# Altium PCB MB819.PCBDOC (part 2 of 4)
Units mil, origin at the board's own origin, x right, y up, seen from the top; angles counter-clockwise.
Board outline 4505 x 6805 mil, 4 copper layers (TopLayer, MidLayer1, GND, BottomLayer), stack 69.6 mil thick; 336 components, 282 nets, 1318 pads, 584 vias.
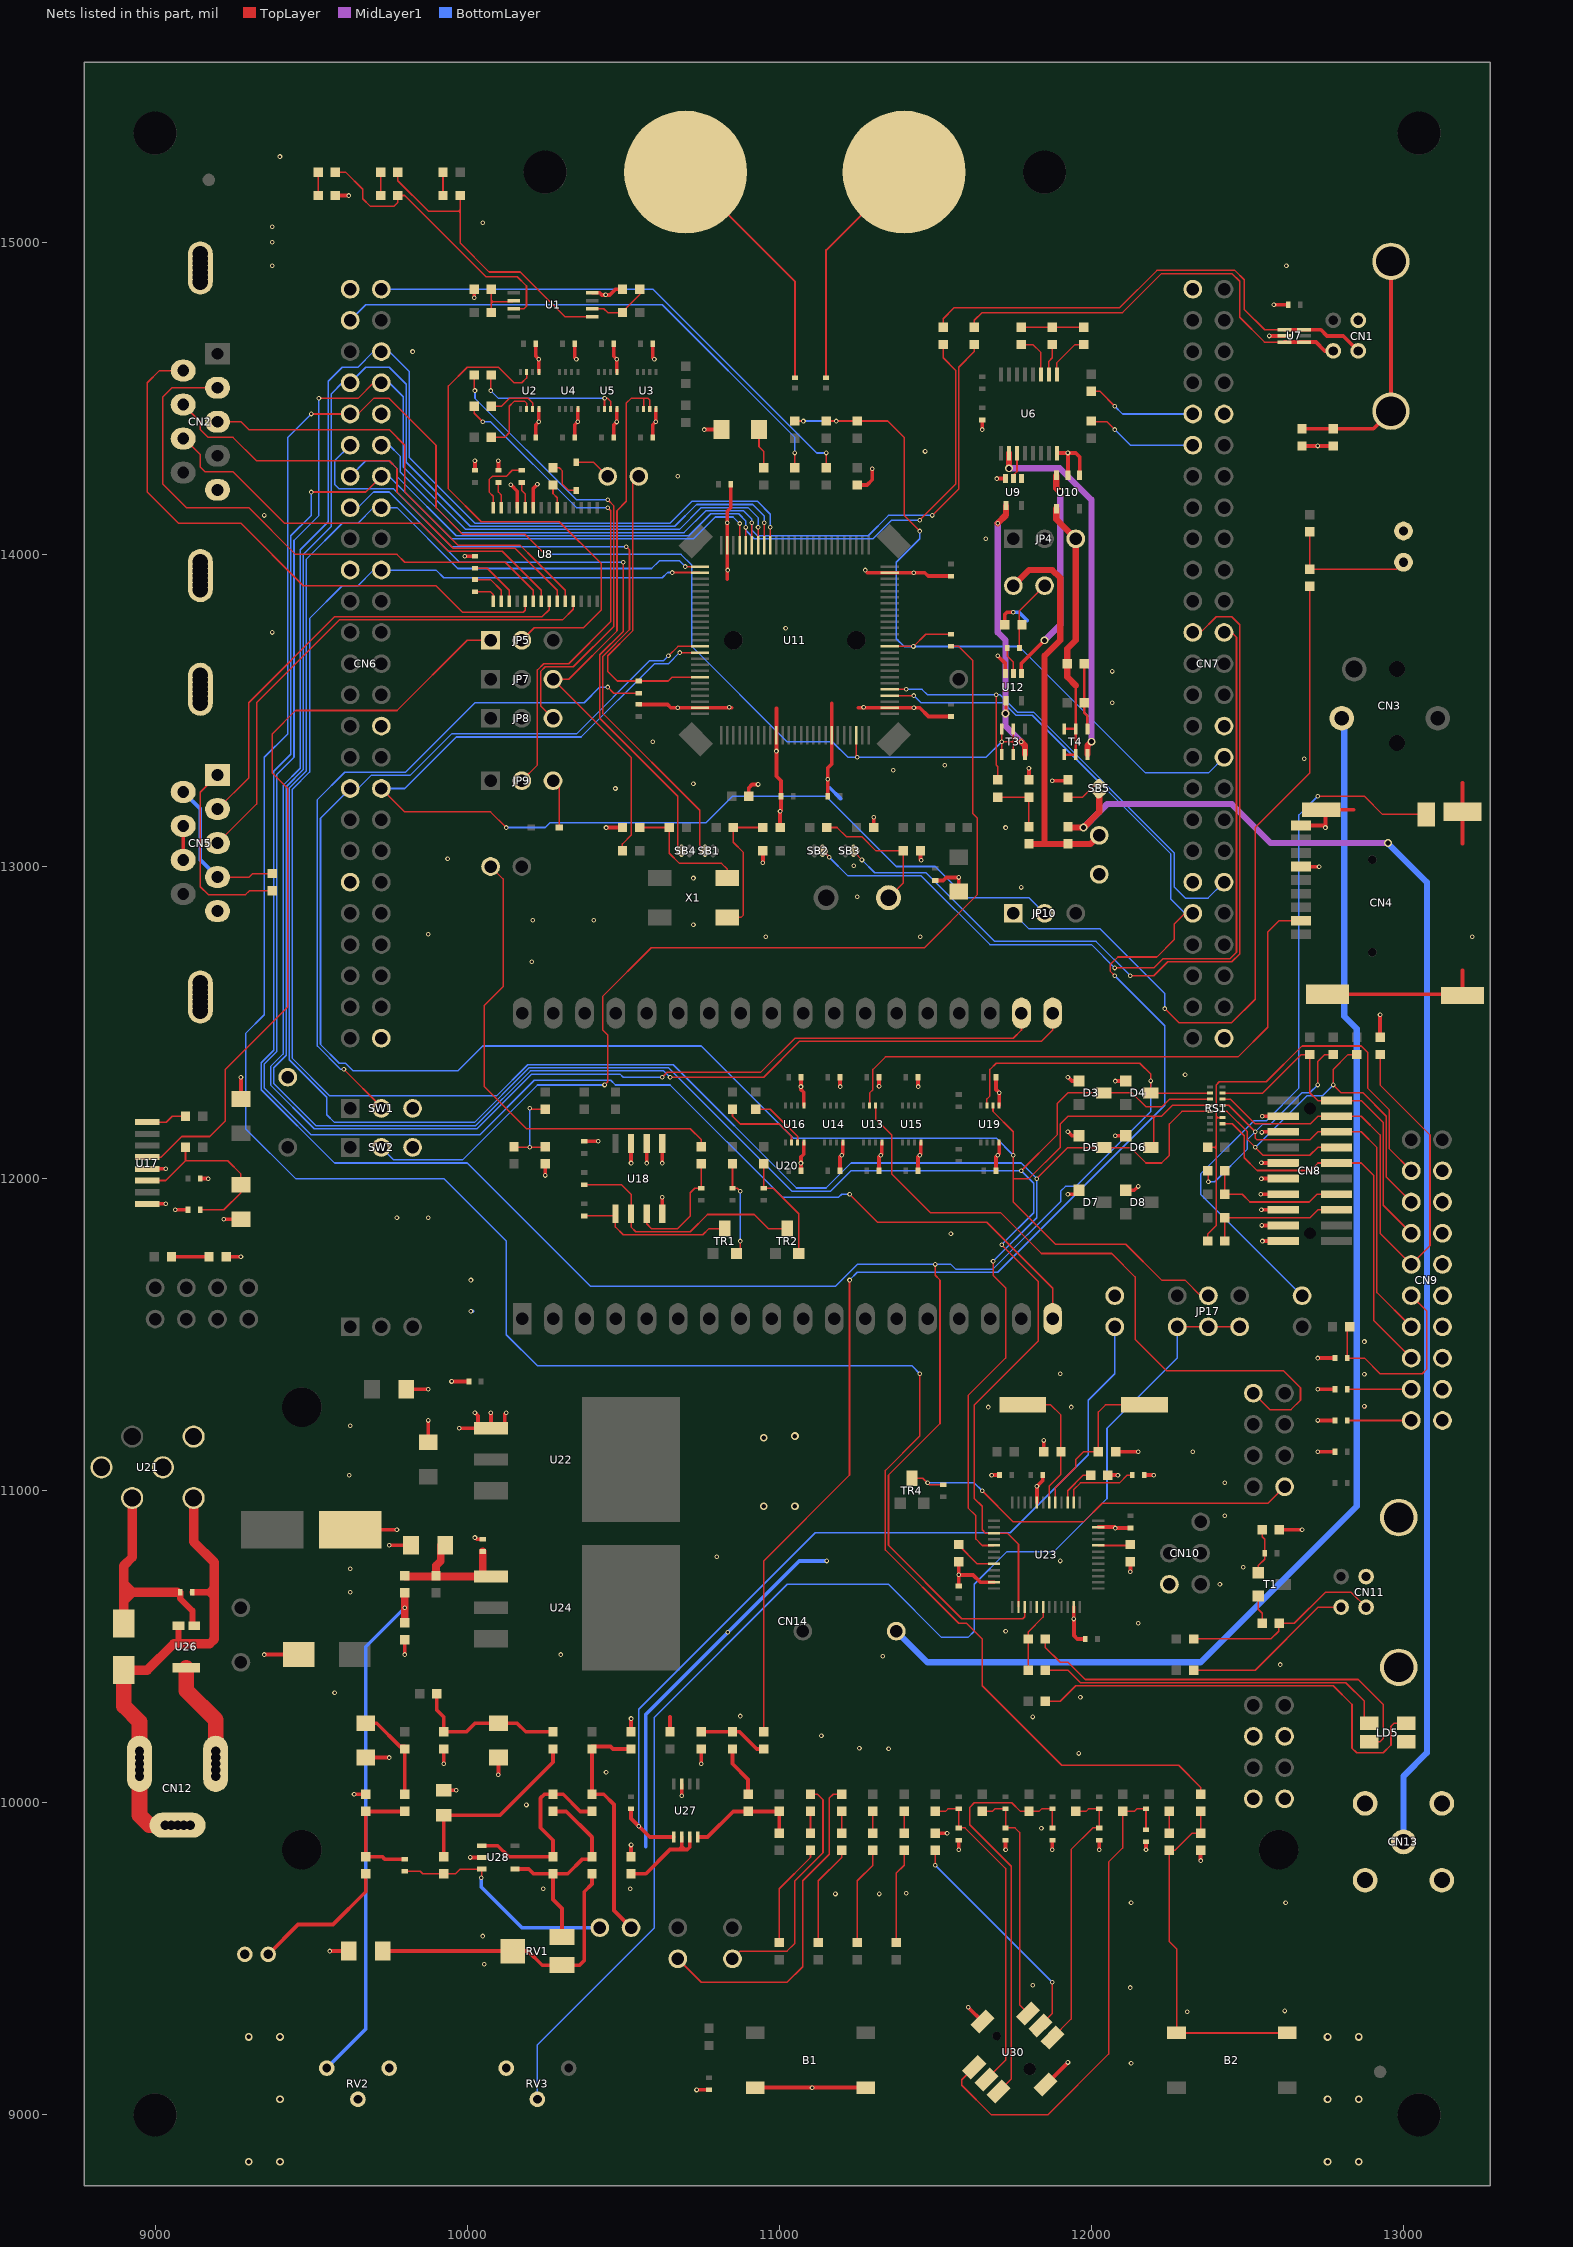
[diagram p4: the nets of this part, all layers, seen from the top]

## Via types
v1: diameter 15, hole 8, TopLayer to BottomLayer, tented both sides, 315 vias
v2: diameter 15, hole 8, TopLayer to BottomLayer, 230 vias
v3: diameter 25, hole 15, TopLayer to BottomLayer, tented both sides, 31 vias
v4: diameter 25, hole 16, TopLayer to BottomLayer, 6 vias
v5: diameter 25, hole 16, TopLayer to BottomLayer, tented both sides, 2 vias

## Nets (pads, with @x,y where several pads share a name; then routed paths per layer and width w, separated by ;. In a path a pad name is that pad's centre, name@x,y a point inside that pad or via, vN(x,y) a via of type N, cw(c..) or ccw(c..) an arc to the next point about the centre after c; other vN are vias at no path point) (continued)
GND: B1.1 B1.4 C1.1 C2.1 C3.1 C4.1 C5.2 C7.2 C8.2 C9.1 C10.1 C11.1 C12.1 C13.1 C14.1 C15.2 C17.2 C18.2 C20.2 C21.2 C22.2 C23.2 C24.2 C25.2 C26.2 C27.2 C28.2 C29.2 C30.2 C31.1 C32.2 C33.2 C34.2 C35.1 C36.1 C37.1 C38.1 C39.2 C40.2 C41.1 C42.1 C43.1 C44.2 C45.2 C46.1 C47.2 C48.2 C49.2 C50.1 C51.2 C52.2 C53.1 C54.1 C55.2 C56.1 C57.2 C58.2 C59.1 C62.1 C63.2 C64.1 C65.2 C66.2 C67.2 C68.2 C69.2 C70.1 C72.2 C73.2 C76.1 C77.1 C78.1 C79.1 C80.1 C83.2 C84.2 C85.1 CN1.4 CN2.0 CN2.5 CN4.6 CN4.9 CN4.G1 CN4.G2 CN4.G3 CN4.G4 CN5.0 CN5.5 CN6.1 CN6.10 CN6.19 CN6.30 CN6.39 CN6.50 CN7.1 CN7.10 CN7.30 CN7.39 CN7.50 CN8.3 CN8.5 CN8.9 CN8.11 CN8.13 CN8.15 CN8.17 CN8.19 CN9.4 CN9.6 CN9.8 CN9.10 CN9.12 CN9.14 CN9.16 CN9.18 CN9.20 CN10.2 CN11.0 CN11.4 CN13.1 CN13.2 CN13.3 CN13.4 CN14.11 CN14.12 CN14.15 CN14.16 D3.2 D4.2 D5.2 D6.2 D7.2 D8.2 JP16.2 LD5.1 LD9.2 R2.2 R4.1 R6.1 R8.2 R15.2 R27.1 R34.1 R40.1 R42.2 R54.1 R56.2 R79.1 R80.1 R81.2 R83.1 R84.1 R85.2 R89.1 R93.1 R100.2 R132.1 R134.2 RV2.1 RV2.2 RV3.3 SW1.3 SW2.3 TP2.1 TP4.1 U1.4 U2.4 U2.5 U3.4 U4.4 U5.4 U5.5 U6.8 U7.2 U8.23 U8.25 U9.3 U10.1 U10.2 U11.10 U11.19 U11.27 U11.49 U11.74 U11.99 U12.3 U13.4 U14.4 U15.4 U16.4 U16.5 U17.5 U17.8 U18.4 U18.5 U18.6 U18.7 U19.4 U19.5 U21.4 U21.5 U21.6 U22.1 U23.8 U23.23 U23.35 U23.47 U27.7 U28.2 U29.1 U30.G | length 11978.2
  TopLayer w12: U17.8@8975,11919.09 v1(9034.09,11919.09) ; U17.5@8975,12031.3 v1(9033.7,12031.3) ; v1(9065,11900) C47.2@9105.5,11900 ; C44.2@9144.5,12000 v1(9170,12000) ; v1(9220,11870) C48.2@9275,11870 ; LD9.2@9227.5,11750 v1(9275,11750) ; C40.2@9275,12255 v2(9275,12325) ; v1(9350,10475) C65.2@9460,10475 ; v1(9560,9525) C84.2@9620,9525 ; R2.2@9577.5,15150 v2(9620,15150) ; C58.2@9625,10875 v1(9775,10875) ; v1(9637.5,10027.5) C72.2@9675,10027.5 ; C67.2@9675,10145 v1(9750,10145) ; v2(9750,10825) C39.2@9820,10825 ; v1(9800,10475) R56.2@9800,10522.5 ; C52.2@9805,11325 v2(9875,11325) ; C55.2@9875,11155 v1(9875,11225) ; C73.2@9925,10040 v1(9965,10040) ; v1(9925,10125) R100.2@9925,10172.5 ; v1(9950,11350) C51.2@10005.5,11350 ; v2(9975,11200) U22.1@10076.18,11200 10076.18,11248.82 v2(10075,11250) ; v2(9992.5,13994.5) C20.2@10025,13994.5 ; v1(10010,9825) U28.2@10046.85,9825 ; v1(10022.5,14822.5) R4.1@10022.5,14850 ; v2(10025,10850) 10030.5,10844.5 C63.2@10050,10844.5 ; v2(10025,11250) 10035,11240 U22.1@10035,11200 ; C14.1@10025,14269.5 v1(10025,14300) ; v1(10100,10090) C68.2@10100,10145 ; C15.2@10100,14269.5 v2(10100,14300) ; U22.1@10120,11200 10120,11245 v2(10125,11250) ; v1(10140,14223) 10160.43,14202.57 U8.25@10160.43,14149.61 ; U8.23@10211.61,14149.61 10211.61,14211.61 v2(10225,14225) ; C8.2@10219.5,14375 10219.5,14414.97 v2(10229.53,14425) U2.4@10229.53,14465.94 ; C4.1@10219.5,14675 10219.5,14635.5 v1(10229.53,14625.47) U2.5@10229.53,14584.06 ; v2(10250,12010) R81.2@10250,12047.5 ; C9.1@10344.5,14375 10344.5,14415.44 v1(10354.53,14425.47) ; C1.1@10344.5,14675 10344.5,14630.5 v1(10350,14625) ; U4.4@10354.53,14465.94 v1(10354.53,14425.47) ; v1@10355,14425 v1(10354.53,14425.47) ; C41.1@10375.5,12120 v1(10420,12120) ; U1.4@10400.98,14838.39 10425,14838.39 10431.77,14831.61 10456.61,14831.61 10475,14850 R6.1@10497.5,14850 ; v1(10445,13125) C28.2@10497.5,13125 ; C10.1@10469.5,14375 10469.5,14414.5 v2(10479.53,14424.53) U5.4@10479.53,14465.94 ; C2.1@10469.5,14675 10469.5,14635.03 v1(10479.53,14625) U5.5@10479.53,14584.06 ; C83.2@10525,9827.5 v1(10525,9865) ; C69.2@10525,10227.5 v1(10525,10270) ; v1(10525,12050) U18.7@10525,12112.5 ; C23.2@10550,13519.5 10641.5,13519.5 10652.54,13508.46 v1@10846.54,13508.46 ; v1(10575,12050) U18.6@10575,12112.5 ; C12.1@10594.5,14375 10594.5,14415.44 v1(10604.53,14425.47) U3.4@10604.53,14465.94 ; C3.1@10594.5,14675 10594.5,14630.5 v1(10600,14625) ; U18.4@10625,11887.5 v1(10625,11940) ; v1@10625,12052.5 U18.5@10625,12115 ; C66.2@10650,10227.5 10650,10275 ; v1(10687.2,10022.2) U27.7@10687.2,10059.69 ; v1(10735,9080) 10735.5,9080.5 C85.1@10775,9080.5 ; v1(10750,10125) C70.1@10750,10172.5 ; v2(10760,14400) C11.1@10815,14400 ; 10833.46,13921.54 10833.46,14138.46 10844.5,14149.5 C17.2@10844.5,14225 ; C22.2@10902.5,13225 10902.5,13252.5 10913,13263 v1(10932.07,13263) ; B1.1@10922.83,9087.5 B1.4@11277.17,9087.5 ; v1(10947.5,13012.5) C30.2@10947.5,13050 ; 10990.94,13505.94 10990.94,13370.06 v1(10991,13370) 10991,13289 11005.5,13274.5 v1@11005.5,13180.5 ; C29.2@11002.5,13125 v1(11002.5,13177.5) ; C45.2@11069.5,12025 11069.5,12069.5 11075,12075 ; v1(11069.5,12295) v1@11070,12295 ; C38.1@11069.5,12325 11069.5,12285.5 11078.53,12276.47 U16.5@11078.53,12234.06 ; 11078.53,12078.53 U16.4@11078.53,12115.94 ; C27.2@11155.5,13225 11155.5,13315.5 11168.11,13328.11 11168.11,13523.11 ; C46.1@11194.5,12025 11194.5,12069.5 v2(11200,12075) ; C35.1@11194.5,12325 11194.5,12295.5 v1(11195,12295) ; v2@11203.53,12078.53 U14.4@11203.53,12115.94 ; C18.2@11250,14222.5 11281.5,14222.5 11298,14239 v1(11298,14275) ; 11253.46,13508.46 11450,13508.46 11477.96,13480.5 C24.2@11550,13480.5 ; 11281.54,13941.54 11466,13941.54 11477.04,13930.5 C21.2@11550,13930.5 ; R40.1@11302.5,13125 v1(11302.5,13157.5) ; C42.1@11319.5,12025 11319.5,12069.5 v2(11325,12075) ; v1(11319.5,12295.5) C36.1@11319.5,12325 ; v2@11328.53,12078.53 U13.4@11328.53,12115.94 ; C43.1@11444.5,12025 11444.5,12069.5 11453.53,12078.53 U15.4@11453.53,12115.94 ; C37.1@11444.5,12325 11444.5,12295.5 v1(11445,12295) ; C33.2@11452.5,13050 11452.5,13022.5 v1(11455,13020) ; R132.1@11500,9902.5 v1(11537.5,9902.5) ; C32.2@11500,12955.5 11525.5,12955.5 11535,12965 v1(11575,12965) C34.2@11575,12920 ; v1(11575,9850) C76.1@11575,9880.5 ; C62.1@11575,10694.5 R15.2@11575,10772.5 ; v2@11575,10730 11621,10730 11644.58,10706.42 U23.23@11687.68,10706.42 ; v2(11605,9345) U30.G@11651,9298.99 ; v2(11650,14400) C7.2@11650,14430.5 ; v1(11680,11050) C56.1@11705.5,11050 ; C50.1@11694.5,12025 11694.5,12069.5 v2(11700,12075) ; C49.2@11694.5,12325 11694.5,12285.5 v2(11704.53,12275.47) U19.5@11704.53,12234.06 ; v1(11697,14243) 11697.31,14243.31 U9.3@11724.41,14243.31 ; v1(11700,13675) 11724.41,13650.59 U12.3@11724.41,13618.31 ; v2@11704.53,12079.53 U19.4@11704.53,12115.94 ; C25.2@11722.5,13775 11722.5,13807.5 11730,13815 v2(11750,13815) ; v1(11725,9850) C77.1@11725,9880.5 ; C31.1@11800,13277.5 v2(11800,13315) ; U23.8@11825.47,10962.32 v1(11825.47,11014.47) 11844.5,11033.5 C57.2@11844.5,11050 ; v1@11826,11015 v1@11827,11015 ; v1(11847,11161) 11847.5,11160.5 C53.1@11847.5,11125 ; U30.G@11852.53,9097.47 11854.47,9097.47 v1(11925,9168) ; v1(11875,9850) C78.1@11875,9880.5 ; v1(11875,13275) R42.2@11922.5,13275 ; U6.8@11890.55,14325 11950,14325 11962.4,14312.6 U10.1@11962.4,14253.15 ; v1(11925,11950) D7.2@11960,11950 ; v2(11925,12150) 11937.5,12137.5 D5.2@11960,12137.5 ; v2(11925,12325) 11937.5,12312.5 D3.2@11960,12312.5 ; U10.2@11925,14253.15 v2(11925,14325) ; U23.35@11943.58,10627.68 11943.58,10589.42 v1(11944,10589) 11944,10536 11955,10525 C64.1@11980.5,10525 ; U23.47@12022.32,10883.58 v1@12073.42,10883.58 ; v1(12025,9850) C79.1@12025,9880.5 ; R79.1@12052.5,11050 v2(12085,11050) ; v1(12076.5,10880.5) C59.1@12125,10880.5 ; v1(12076.5,12137.5) D6.2@12110,12137.5 ; v1(12076.5,12312.5) D4.2@12110,12312.5 ; C54.1@12077.5,11125 v1(12150,11125) ; D8.2@12110,11962.5 12137.5,11962.5 v2(12150,11975) ; v1(12125,10740) R93.1@12125,10773.5 ; R80.1@12169.5,11050 v2(12200,11050) ; v1(12175,9850) C80.1@12175,9875 ; v1(12350,9815) R134.2@12350,9847.5 ; v1(12543,11950) CN8.13@12615,11950 ; v1(12545,11900) CN8.15@12615,11900 ; v1(12545,12000) CN8.11@12615,12000 ; v1(12545,12051) 12546,12050 CN8.9@12615,12050 ; v1(12546,11850) CN8.17@12615,11850 ; v1(12546,12148) 12548,12150 CN8.5@12615,12150 ; v1(12547,12200) CN8.3@12615,12200 ; v1(12548,11800) CN8.19@12615,11800 ; v1(12570,14700) U7.2@12618.7,14700 ; v2(12585,14800) C5.2@12630.5,14800 ; R8.2@12602.5,10875 v2(12675,10875) ; CN4.6@12671.65,12999.61 v1(12729.61,12999.61) ; CN4.9@12671.65,13131.5 12743.5,13131.5 ; R27.1@12675,14347.5 C13.1@12775,14347.5 ; v2(12725,11125) R85.2@12780.5,11125 ; v2(12725,11225) R89.1@12780,11225 ; v2(12725,11325) R84.1@12780.5,11325 ; v2(12725,11425) R83.1@12780.5,11425 ; CN4.G4@12736.61,13181.69 12840.31,13181.69 ; v1(12750,13125) CN4.G4@12750,13176.69 ; CN4.G1@12756.3,12591.14 CN4.G3@13185.43,12591.14 ; v1@12875,11268 v1(12875,11271) ; R54.1@12925,12452.5 v2(12925,12525) ; CN4.G3@13189.37,12587.21 13189.37,12667.37 ; 13189.37,13073.63 13189.37,13267.37
  BottomLayer w12: v1(10012,11575) v1@10018,11575 ; 10572.5,9860 10572.5,10283.61 11063.89,10775 v1(11152,10775) ; 11161.46,13252.43 11196.38,13217.51 ; v2(11750,13815) 11767.72,13815 11794.72,13788
  other v1: 11105,9087.5 12127,9165 12307,9330 12620,9333 12125,9408 11812,9415 10055,9483 10050,9573 12127,9680 12622,9680 11180,9708 11320,9708 11407,9710 10244,9725 10522,9725 11840,9918 10190,9993 10445,10098 11960,10158 11350,10173 11257,10175 11135,10215 11812,10275 10875,10278 11965,10338 9575,10353 12605,10443 11332,10470 10300,10475 10835.31,10546.42 11725,10550 12150,10575 9625,10675 12412,10700 9625,10750 12487,10755 11900,10775 10800,10788 12427,10920 12427,11025 9622,11050 12325,11125 9625,11208 11670,11268 11935,11268 12875,11373 11900,11375 12875,11478 10012,11675 9775,11875 9875,11875 10625,12050 10957,12775 11452,12775 13220,12775 10725,12813 10405,12828 11250,12903 11775,12933 10725,12963 11725,13125 10475,13250 10725,13265 11155.5,13280 11530,13325 10595,13400 10675,13508.47 11431.46,13508.46 10840,13510 11270,13510 12067,13525 12067,13625 9375,13750 11020,13763 11430.46,13941.54 10835,13950 11275,13950 10833.46,14102 9350,14125 10675,14250 12725,14347.5 9825,14650 10443.39,14831.61 9375,14925 12625,14925 9375,15000 9375,15050 10050,15063 9400,15275
  other v2: 11575,10731 11550,11823 11069.5,12050 11450,12075 12300,12333 10207,12695 9875,12783 10210,12828 11238.28,13002.5 9937,13025 11365,13308 12682,13345 11662,14050 11467,14330
  other v3: 9300,8850 9400,8850 12757,8850 12857,8850 9400,9050 12757,9050 12857,9050 9300,9250 9400,9250 12757,9250 12857,9250 10950,10950 11050,10950 10950,11170 11050,11175
IRDA_RXD: JP5.1 U17.4 | length 2466
  TopLayer w5: U17.4@8975,12068.7 9018.7,12068.7 9085,12135 9175,12135 9225,12185 9225,12350 9425,12550 9425,13250 9375,13300 9375,13425 9450,13500 9775,13500 10000,13725 JP5.1@10075,13725
LCD_CS_3V3: CN14.1 U13.6 | length 2176.4
  TopLayer w5: U13.6@11308.84,12234.06 11308.84,12191.16 11360,12140 11360,12015 11485,11890 11710,11890 11840,11760 12065,11760 12140,11685 12140,11485 12240,11385 12615,11385 12670,11330 12670,11290 12640,11260 12571.73,11260 CN14.1@12519.02,11312.72
LED_STLINK: R92.1 R105.2 U23.30 | length 222.4
  TopLayer w5: R92.1@11797.5,10425 11797.5,10547.5 11845.16,10595.16 U23.30@11845.16,10627.68
MCO: U23.29
MICROSD_CS_3V3: CN4.2 U13.7 | length 1870
  TopLayer w5: U13.7@11289.16,12234.06 11289.16,12274.16 11300,12285 11300,12350 11340,12390 12470,12390 12565,12485 12565,12790 12601.38,12826.38 CN4.2@12671.65,12826.38 CN4.2@12673.03,12825
NC: U9.1
NetC6_2: C6.2 R17.2 R18.2 | length 200
  TopLayer w5: R17.2@11775,14727.5 C6.2@11975,14727.5
NetC11_2: C11.2 R29.2 | length 128.7
  TopLayer w5: C11.2@10935,14400 10935,14345 10950,14330 R29.2@10950,14277.5
NetC13_2: C13.2 CN1.0 R27.2 | length 788.4
  TopLayer w12: R27.2@12675,14402.5 12903.5,14402.5 CN1.0@12960,14459 CN1.0@12960,14939
NetC16_1: C16.1 U8.24 | length 85.5
  TopLayer w5: C16.1@10175,14230.5 10175,14205 10186.02,14193.98 U8.24@10186.02,14149.61
NetC16_2: C16.2 U8.28 | length 213.3
  TopLayer w5: U8.28@10083.66,14149.61 10083.66,14186.34 10070,14200 10070,14240 10080,14250 10125,14250 10144.5,14269.5 C16.2@10175,14269.5
NetC19_1: C19.1 U8.1 | length 83.4
  TopLayer w5: C19.1@10025,13880.5 10074.5,13880.5 10083.66,13871.34 U8.1@10083.66,13850.39
NetC19_2: C19.2 U8.2 | length 133.1
  TopLayer w5: C19.2@10025,13919.5 10074.75,13919.5 10109.25,13885 U8.2@10109.25,13850.39
NetC28_1: C28.1 R38.1 X1.4 | length 413
  TopLayer w5: C28.1@10552.5,13125 R38.1@10647.5,13125 10647.5,13042.5 10680,13010 10815,13010 10833.27,12991.73 X1.4@10833.27,12962.99
NetC31_2: C31.2 R45.2 R47.1 | length 195
  TopLayer w5: R45.2@11700,13222.5 C31.2@11800,13222.5 R47.1@11800,13127.5
NetC33_1: C33.1 R39.2 X2.1 | length 445.7
  TopLayer w5: R39.2@11152.5,13125 11185,13125 11215,13095 11265,13095 11310,13050 C33.1@11397.5,13050 11397.5,12947.5 X2.1@11350,12900
NetC67_1: C67.1 R99.1 R106.2 | length 308.9
  TopLayer w12: C67.1@9675,10255 9710,10255 9784.5,10180.5 9800,10180.5 R106.2@9800,10027.5
NetC68_1: C68.1 R98.2 R100.1 R101.1 | length 504.6
  TopLayer w12: R98.2@9902.5,10350 9902.5,10297.5 9925,10275 R100.1@9925,10227.5 9997.5,10227.5 10025,10255 10160,10255 10187.5,10227.5 R101.1@10275,10227.5
NetC71_2: C71.2 R110.1 | length 165.7
  TopLayer w12: C71.2@10850,10172.5 10850,10125 10900,10075 R110.1@10900,10027.5
NetC75_2: C75.2 R129.2 TP8.1 U28.3 | length 748.6
  TopLayer w5: C75.2@9800,9780.5 9849.5,9780.5 9857.5,9772.5 9962.5,9772.5 9977.6,9787.6 U28.3@10046.85,9787.6 10046.85,9761.85 v1(10045,9760)
  BottomLayer w12: v1(10045,9760) 10045,9730 10175,9600 TP8.1@10425,9600
NetC81_1: C81.1 R133.2 | length 70
  TopLayer w5: C81.1@12250,9902.5 R133.2@12250,9972.5
NetC81_2: B2.2 B2.3 C81.2 R120.1 R134.1 | length 1141.6
  TopLayer w5: R120.1@12350,9972.5 R134.1@12350,9902.5 12322.5,9902.5 12267.5,9847.5 C81.2@12250,9847.5 12250,9555 12272.83,9532.17 B2.2@12272.83,9262.5 B2.3@12627.17,9262.5
NetC82_2: C82.2 R107.1 R108.2 U28.1 | length 1279.3
  TopLayer w5: U28.1@10046.85,9862.4 10097.6,9862.4 10132.5,9827.5 C82.2@10275,9827.5 10275,9880 10235,9920 10235,10015 10247.5,10027.5 10307.5,10027.5 10362.5,9972.5 R108.2@10400,9972.5
  TopLayer w12: U28.1@10046.85,9862.4 10097.6,9862.4 10132.5,9827.5 C82.2@10275,9827.5 10275,9880 10235,9920 10235,10015 10247.5,10027.5 10307.5,10027.5 10362.5,9972.5 R108.2@10400,9972.5
NetCN1_2: CN1.2 R16.2 U7.3 U7.4 | length 1404.7
  TopLayer w5: R16.2@11625,14727.5 11625,14750 11650,14775 12100,14775 12225,14900 12450,14900 12475,14875 12475,14760 12554.69,14680.31 U7.3@12618.7,14680.31
  TopLayer w12: U7.3@12618.7,14680.31 12719.69,14680.31 12748,14652 CN1.2@12775,14652
NetCN1_3: CN1.3 R25.2 U7.1 U7.6 | length 1584.2
  TopLayer w5: R25.2@11525,14727.5 11525,14755 11560,14790 12090,14790 12210,14910 12460,14910 12490,14880 12490,14785 12555.31,14719.69 U7.1@12618.7,14719.69
  TopLayer w12: U7.1@12618.7,14720 U7.6@12681.3,14720 ; U7.6@12681.3,14719.69 12735.31,14719.69 12755,14700 12807,14700 CN1.3@12855,14652
NetCN3_10: CN3.10 U25.1 | length 4258
  BottomLayer w20: U25.1@11374.61,10550 11474.61,10450 12350,10450 12850,10950 12850,12480 12810,12520 CN3.10@12810,13467.56
NetCN4_10: CN4.10 JP2.1 | length 2285.7
  TopLayer w5: v2(12725,13225) 12875,13225 12933.07,13166.93 CN4.10@13073.23,13166.93
  BottomLayer w5: JP2.1@12675,11625 12350,11950 12350,12015.15 12519.85,12185 12560,12185 12665,12290 12665,13165 v2(12725,13225)
NetCN5_7: CN5.7 CN5.8 | length 109
  TopLayer w12: CN5.8@9090,13021 CN5.7@9090,13130
NetCN6_2: CN6.2 R30.2 | length 1690
  TopLayer w5: R30.2@11150,14277.5 v1(11150,14325)
  BottomLayer w5: CN6.2@9725,14850 10595,14850 11120,14325 v1(11150,14325)
NetCN8_14: CN8.14 R65.1 R70.1 | length 453.2
  TopLayer w5: R65.1@12427.5,12025 R70.1@12427.5,11950 12483,11950 12508,11925 12698,11925 12723,11950 CN8.14@12785,11950
NetCN8_16: CN8.16 R71.1 R74.1 | length 441.7
  TopLayer w5: R74.1@12427.5,11800 12427.5,11873 12428.5,11874 12700,11874 12726,11900 CN8.16@12785,11900
NetCN9_11: CN9.11 R82.1 R83.2 | length 638.1
  TopLayer w5: R82.1@12819.5,11525 R83.2@12819.5,11425 12875,11425 12925,11375 13060,11375 13075,11390 13075,11575 CN9.11@13025,11625
NetCN9_17: CN9.17 R84.2 | length 205.5
  TopLayer w5: R84.2@12819.5,11325 CN9.17@13025,11325
NetCN9_19: CN9.19 R89.2 | length 205.5
  TopLayer w5: R89.2@12819.5,11225 CN9.19@13025,11225
NetCN11_2: CN11.2 R104.2 | length 556.2
  TopLayer w5: R104.2@12327.5,10425 12525,10425 12727,10627 CN11.2@12800,10627
NetCN11_3: CN11.3 R7.2 R97.2 | length 647.7
  TopLayer w5: R97.2@12327.5,10525 12575,10525 12600,10550 12600,10572.5 R7.2@12602.5,10575 12650,10575 12750,10675 12832,10675 CN11.3@12880,10627
NetCN12_1: CN12.1 U26.1 | length 346.5
  TopLayer w50: U26.1@9100,10432.5 9100,10360 9194.09,10265.9 CN12.1@9194.09,10125
NetCN12_3: C61.2 CN12.2 CN12.3 U21.2 U26.2 Z1.1 | length 1617.6
  TopLayer w5: U21.2@9115,10980 U21.2@9119.5,10975.5
  TopLayer w20: 9075,10515 U26.2@9075,10567.5 ; C61.2@9119.5,10675 9190,10675 ; 9190,10655 9170,10675 9190,10695
  TopLayer w30: Z1.1@8900,10415 Z1.1@8900,10425.2 8975.2,10425.2 9060,10510 9175,10510 9190,10525 9190,10770 9123.43,10836.57 U21.2@9123.43,10976.57
  TopLayer w50: Z1.1@8900,10415 8900,10310 8950,10260 8950,9960 8981.85,9928.15 CN12.2@9072.05,9928.15
NetD1_1: D1.1 R138.1 | length 129.9
  TopLayer w5: R138.1@10275,14277.5 10295,14277.5 10305,14267.5 10305,14225 10325,14205 D1.1@10350,14205
NetD1_2: D1.2 JP6.2 | length 118.6
  TopLayer w5: D1.2@10350,14295 10405,14295 JP6.2@10450,14250
NetD2_2: D2.2 JP9.3 | length 158.3
  TopLayer w5: JP9.3@10275,13275 10295,13255 D2.2@10295,13125
NetJP4_3: JP4.3 R35.1 T4.1 T4.2 T4.5 T4.6 U10.4 | length 911.6
  TopLayer w8: T4.1@11912.6,13358.66 T4.2@11950,13358.66 11950,13580 ; T4.6@11912.6,13441.34 T4.5@11950,13441.34
  TopLayer w20: U10.4@11887.6,14146.85 11887.6,14112.4 JP4.3@11950,14050 11950,13725 11922.5,13697.5 11922.5,13607.5 11950,13580
NetJP7_3: JP7.3 R44.1 U3.2 U3.3 | length 1822.7
  TopLayer w5: R44.1@10497.5,13050 10497.5,13072.5 10525,13100 10525,13350 JP7.3@10275,13600 10325,13600 10480,13755 10480,14140 10510,14170 10510,14485 10525,14500 10580,14500 10584.84,14495.16 U3.3@10584.84,14465.94 ; U3.2@10565.16,14465.94 10565.16,14499.84
NetJP8_3: JP8.3 R11.1 | length 1510.6
  TopLayer w5: R11.1@10022.5,14575 10022.5,14527.5 v2(10025,14525) ; JP8.3@10275,13475 10235,13515 10235,13625 10250,13640 10340,13640 10470,13770 10470,14155 v2(10450,14175)
  BottomLayer w5: v2(10025,14525) 10025,14500 10350,14175 v2(10450,14175)
NetJP9_2: JP9.2 R20.1 | length 1619.4
  TopLayer w5: R20.1@10022.5,14475 10022.5,14452.5 v2(10050,14425) ; JP9.2@10175,13275 10225,13325 10225,13630 10245,13650 10325,13650 10460,13785 10460,14140 v2(10450,14150)
  BottomLayer w5: v2(10050,14425) 10075,14425 10350,14150 v2(10450,14150)
NetJP10_1: JP10.1 R96.2 | length 2374.4
  TopLayer w5: v2(12235,12545) 12280,12500 12450,12500 12525,12575 12525,13125 12700,13300 R96.2@12700,13897.5
  BottomLayer w5: JP10.1@11750,12850 11800,12800 12028.43,12800 12235,12593.43 v2(12235,12545)
NetJP11_2: JP11.2 R61.2 | length 1534.3
  TopLayer w5: JP11.2@10075,13000 10115,12960 10115,12615 10055,12555 10055,12295 10190,12160 10715,12160 10750,12125 R61.2@10750,12102.5
NetJP16_1: JP16.1 R109.1 U27.1 | length 2789.6
  TopLayer w12: R109.1@10525,9980.5 10525,9950 10584.69,9890.31 U27.1@10661.61,9890.31
  BottomLayer w5: v2(10549.99,9925.01) 10549.99,10299.99 11115,10865 11740,10865 11990,11115 11990,11290 12075,11375 JP16.1@12075,11525
NetJP17_5: JP17.1 JP17.3 JP17.5 RV3.2 | length 4213.2
  TopLayer w5: JP17.1@12275,11525 JP17.5@12490,11525 ; JP17.5@12465,11525 JP17.5@12469.5,11520.5
  BottomLayer w5: RV3.2@10225,9050 10225,9225 10600,9600 10600,10274.5 11025.5,10700 11350,10700 11520,10530 11605,10530 11625,10550 11625,10700 11730,10805 11880,10805 12050,10975 12050,11200 12275,11425 JP17.1@12275,11525
NetJP18_1: JP18.1 R124.1 | length 1072.2
  TopLayer w5: JP18.1@10675,9500 10750,9425 11025,9425 11075,9475 11075,9750 11160,9835 11160,10015 11172.5,10027.5 R124.1@11200,10027.5
NetJP19_1: JP19.1 R122.1 | length 775.2
  TopLayer w5: JP19.1@10850,9500 10875,9525 11025,9525 11050,9550 11050,9750 11140,9840 11140,10010 11122.5,10027.5 R122.1@11090,10027.5
NetLD1_2: LD1.2 R136.2 | length 313.4
  TopLayer w5: LD1.2@11375,9552.5 11375,9775 11400,9800 R136.2@11400,9855.5
NetLD2_2: LD2.2 R131.2 | length 331.2
  TopLayer w5: LD2.2@11250,9545 11250,9750 11300,9800 R131.2@11300,9855.5
NetLD3_2: LD3.2 R123.2 | length 334.1
  TopLayer w5: LD3.2@11125,9552.5 11125,9750 11200,9825 R123.2@11200,9855.5
NetLD4_2: LD4.2 R130.2 | length 344.4
  TopLayer w5: LD4.2@11000,9552.5 11000,9725 11100,9825 R130.2@11100,9855.5
NetLD5_3: LD5.3 R92.2 | length 1133.9
  TopLayer w5: R92.2@11852.5,10425 11925,10425 11965,10385 12815,10385 12875,10325 LD5.3@12875,10255
NetLD5_4: LD5.4 R102.1 | length 1422.6
  TopLayer w5: R102.1@11852.5,10325 11900,10325 11950,10375 12775,10375 12835,10315 12835,10175 12850,10160 12935,10160 12960,10185 12960,10245 12969.53,10254.53 LD5.4@13009.06,10254.53
NetLD6_2: LD6.2 R2.1 | length 75
  TopLayer w5: R2.1@9522.5,15150 LD6.2@9522.5,15225
NetLD7_2: LD7.2 R1.1 | length 75
  TopLayer w5: R1.1@9722.5,15150 LD7.2@9722.5,15225
NetLD8_2: LD8.2 R3.1 | length 75
  TopLayer w5: R3.1@9922.5,15150 LD8.2@9922.5,15225
NetR5_1: R4.2 R5.1 U1.6 | length 157.4
  TopLayer w5: R5.1@10077.5,14775.5 R4.2@10077.5,14850 ; 10077.5,14805 10082.5,14810 10077.5,14815 ; 10077.5,14810 U1.6@10146.22,14810
NetR7_1: R7.1 T1.1 | length 92.7
  TopLayer w5: T1.1@12535,10662.5 12535,10620 12547.5,10607.5 R7.1@12547.5,10575
NetR9_1: R6.2 R9.1 U1.2 | length 204
  TopLayer w5: U1.2@10400.98,14787.21 10437.79,14787.21 10450,14775 10505.5,14775 10505.5,14785.5 10552.5,14832.5 R6.2@10552.5,14850
NetR10_2: R8.1 R10.2 T1.2 | length 149.3
  TopLayer w5: T1.2@12535,10737.5 12535,10760 12555.5,10780.5 12555.5,10844.5 12547.5,10852.5 R8.1@12547.5,10875
NetR13_2: R13.2 TS1.1 | length 803.5
  TopLayer w7: TS1.1@10700,15225 11050,14875 R13.2@11050,14566.5
NetR14_2: R14.2 TS2.1 | length 762.1
  TopLayer w7: R14.2@11150,14566.5 11150,14975 TS2.1@11400,15225
NetR28_1: CN6.3 R28.1 | length 1719.3
  TopLayer w5: R28.1@11050,14277.5 v1(11050,14325)
  BottomLayer w5: CN6.3@9625,14750 9675,14800 10625,14800 11050,14375 v1(11050,14325)
NetR31_2: CN7.9 R31.2 | length 355
  TopLayer w5: R31.2@12000,14522.5 12027.5,14522.5 v2(12075,14475)
  BottomLayer w5: v2(12075,14475) 12100,14450 CN7.9@12325,14450
NetR32_1: JP6.1 R32.1 U11.94 | length 971.8
  TopLayer w5: JP6.1@10530,14250 10530,13755 10450,13675 10450,13625 10480.5,13594.5 10644.5,13594.5 10656.89,13606.89 U11.94@10745.87,13606.89
NetR32_2: R32.2 SW1.2 | length 2262.6
  TopLayer w5: v2(9605,12350) SW1.2@9725,12230 ; v2(10450,13575) 10469.5,13555.5 R32.2@10550,13555.5
  BottomLayer w5: v2(9605,12350) 9595,12350 9520,12425 9520,13214.44 9607.6,13302.03 9802.03,13302.03 10025,13525 10375,13525 10425,13575 v2(10450,13575)
NetR33_2: C25.1 JP14.2 R33.2 | length 233.3
  TopLayer w5: R33.2@11769.5,13700 11769.5,13819.5 JP14.2@11850,13900
NetR34_2: R34.2 R53.1 R96.1 | length 429.3
  TopLayer w5: R53.1@12700,14072.5 R96.1@12700,13952.5 12977.5,13952.5 R34.2@13000,13975
NetR36_1: R35.2 R36.1 T4.4 | length 212.8
  TopLayer w8: R35.2@11977.5,13650 11977.5,13492.5 11987.4,13482.6 T4.4@11987.4,13441.34
NetR43_2: R43.2 SW2.2 | length 3306
  TopLayer w5: v2(10440,12300) 10450,12310 10450,12460 10435,12475 10435,12585 10590,12740 11465,12740 11635,12910 11635,13155 11620,13170 11620,13660 11574.5,13705.5 R43.2@11550,13705.5
  BottomLayer w5: SW2.2@9725,12100 9765,12060 9985,12060 10225,12300 v2(10440,12300)
NetR46_1: CN5.4 CN5.6 R46.1 | length 498.3
  TopLayer w5: CN5.4@9200,12966 9301,12966 9312.5,12977.5 R46.1@9375,12977.5
  BottomLayer w12: CN5.6@9090,13239 9145,13184 9145,13021 CN5.4@9200,12966
NetR46_2: CN5.1 R46.2 | length 626.3
  TopLayer w5: CN5.1@9200,13293 9145,13238 9145,12935 9170,12910 9290,12910 9302.5,12922.5 R46.2@9375,12922.5
NetR47_2: JP14.1 R47.2 R48.1 TP3.1 | length 1290.7
  TopLayer w20: JP14.1@11750,13900 11800,13950 11875,13950 11900,13925 11900,13725 11850,13675 11850,13072.5 ; R47.2@11800,13072.5 11997.5,13072.5 TP3.1@12025,13100
NetR48_2: CN13.5 R48.2 SB5.1 | length 4508.3
  TopLayer w5: SB5.1@12032,13232 SB5.1@12033,13232
  TopLayer w20: R48.2@11927.5,13125 v4(11975,13125) 12025,13175 SB5.1@12025,13223.4
  MidLayer1 w20: v4(11975,13125) 12050,13200 12450,13200 12575,13075 v4(12950,13075)
  BottomLayer w20: v4(12950,13075) 13075,12950 13075,10160 13000,10085 CN13.5@13000,9875
NetR49_1: CN7.11 R49.1 | length 356.1
  TopLayer w5: R49.1@12000,14427.5 R49.1@12002.5,14427.5 ; R49.1@12002.5,14425 12050,14425 v2(12075,14400)
  BottomLayer w5: v2(12075,14400) 12125,14350 CN7.11@12325,14350
NetR55_2: R55.2 U17.1 | length 130.4
  TopLayer w5: U17.1@8975,12180.91 9035.91,12180.91 9055,12200 R55.2@9097.5,12200
NetR60_2: C47.1 C48.1 R60.2 U17.6 | length 599.7
  TopLayer w5: U17.6@8975,11993.9 9033.9,11993.9 9097.5,12057.5 ; R60.2@9097.5,12100 9097.5,12057.5 ; C47.1@9144.5,11900 9220,11900 9275,11955 9275,12015 9232.5,12057.5 9097.5,12057.5
NetR61_1: R61.1 R67.1 U18.3 | length 389.3
  TopLayer w5: U18.3@10575,11887.5 10575,11855 10590,11840 10675,11840 10715,11880 10715,11955 10729.5,11969.5 R67.1@10750,11969.5 R61.1@10750,12047.5
NetR62_2: R62.2 R73.1 TR1.1 | length 306.9
  TopLayer w5: R62.2@10850,12047.5 R73.1@10850,11969.5 10865.5,11969.5 v2(10875,11960) ; TR1.1@10875,11760 v2(10875,11800)
  BottomLayer w5: v2(10875,11800) v2(10875,11960)
NetR69_2: R68.1 R69.2 TR2.1 | length 352
  TopLayer w5: R69.2@10950,12047.5 R68.1@10950,11969.5 10980.5,11969.5 11062.5,11887.5 TR2.1@11062.5,11760
NetR72_1: LD9.1 R72.1 | length 128
  TopLayer w12: R72.1@9044.5,11750 LD9.1@9172.5,11750
NetR79_2: R79.2 U23.3 | length 132
  TopLayer w5: U23.3@11923.9,10962.32 11923.9,11000 11973.9,11050 R79.2@11997.5,11050
NetR80_2: R80.2 U23.2 | length 247.4
  TopLayer w5: U23.2@11943.58,10962.32 11943.58,11003.58 11965,11025 12090,11025 12115,11050 R80.2@12130.5,11050
NetR86_2: R81.1 R86.2 R88.2 | length 271
  TopLayer w5: R86.2@10152.5,12100 R81.1@10247.5,12100 ; v2(10200,12225) 10202.5,12222.5 R88.2@10250,12222.5
  BottomLayer w5: v2(10200,12100) v2(10200,12225)
NetR91_1: CN14.8 R91.1 TR4.3 | length 1350.5
  TopLayer w5: TR4.3@11425.5,11040 11460,11040 11480.5,11019.5 R91.1@11525,11019.5 ; v2(11650,11000) 11750,10900 11975,10900 12035,10960 12566.3,10960 CN14.8@12619.02,11012.72
  BottomLayer w5: v2(11475,11025) 11625,11025 v2(11650,11000)
NetR95_1: C39.1 C63.1 R94.1 R95.1 U24.1 | length 455.4
  TopLayer w25: R95.1@9802.5,10725 U24.1@10076.18,10725 ; R94.1@9900,10727.5 9900,10760 9915,10775 C39.1@9915,10825 ; U24.1@10050,10727.5 C63.1@10050,10805.5
NetR101_2: C73.1 R101.2 R129.1 | length 1190.8
  TopLayer w5: R129.1@9925,9827.5 C73.1@9925,9960 10105,9960 10275,10130 R101.2@10275,10172.5
  TopLayer w12: R129.1@9925,9827.5 C73.1@9925,9960 10105,9960 10275,10130 R101.2@10275,10172.5
NetR103_2: C70.2 C71.1 R103.2 | length 232.8
  TopLayer w5: C70.2@10740,10227.5 C70.2@10750,10227.5
  TopLayer w12: C70.2@10750,10227.5 10872.5,10227.5 10927.5,10172.5 R103.2@10950,10172.5
NetR105_1: LD5.2 R105.1 | length 1343
  TopLayer w5: R105.1@11852.5,10525 11852.5,10497.5 11900,10450 11925,10450 11980,10395 12855,10395 12935,10315 12935,10205.97 12924.5,10195.47 LD5.2@12890.94,10195.47
NetR110_2: C74.1 R110.2 R121.1 U27.4 | length 365.7
  TopLayer w12: U27.4@10738.39,9890.31 10770.31,9890.31 10852.5,9972.5 C74.1@11000,9972.5 R121.1@11000,9902.5
NetR112_1: C76.2 R112.1 R113.2 U30.2 | length 1044.4
  TopLayer w5: R112.1@11500,9972.5 11532.5,9972.5 11540.5,9980.5 R113.2@11575,9980.5 C76.2@11575,9919.5 11595,9919.5 11725,9789.5 11725,9175 11680.91,9130.91 U30.2@11663.7,9113.7
NetR117_1: C79.2 R116.1 R117.1 U30.4 | length 885.5
  TopLayer w5: U30.4@11875.27,9247.33 11935,9307.05 11935,9850 12004.5,9919.5 C79.2@12025,9919.5 R116.1@12025,9980.5 11990.5,9980.5 11982.5,9972.5 R117.1@11950,9972.5
NetR118_1: C80.2 R118.1 R119.1 U30.1 | length 1605.2
  TopLayer w5: U30.1@11624.72,9152.67 11585,9112.95 11585,9095 11680,9000 11860,9000 12055,9195 12055,9810 12100,9855 R118.1@12100,9972.5 12137.5,9972.5 12145.5,9980.5 R119.1@12175,9980.5 C80.2@12175,9914
NetR123_1: R123.1 R124.2 | length 78
  TopLayer w5: R123.1@11200,9894.5 R124.2@11200,9972.5
NetR126_1: C77.2 R114.1 R126.1 U30.6 | length 781.4
  TopLayer w5: R126.1@11650,9972.5 11682.5,9972.5 11690.5,9980.5 R114.1@11725,9980.5 C77.2@11725,9919.5 11755.5,9919.5 11770,9905 11770,9352.6 U30.6@11797.33,9325.27
NetR127_1: C78.2 R115.1 R127.1 U30.3 | length 1329.1
  TopLayer w5: U30.3@11702.67,9074.73 11743.18,9115.23 11743.18,9796.82 11610,9930 11610,9985 11625,10000 11745,10000 11772.5,9972.5 11832.5,9972.5 11840.5,9980.5 R115.1@11875,9980.5 C78.2@11875,9919.5
NetR128_1: C72.1 C75.1 R106.1 R128.1 | length 796.6
  TopLayer w5: C75.1@9800,9819.5 9735.5,9819.5 9727.5,9827.5 R128.1@9675,9827.5 C72.1@9675,9972.5 R106.1@9800,9972.5
  TopLayer w12: C75.1@9800,9819.5 9735.5,9819.5 9727.5,9827.5 R128.1@9675,9827.5 C72.1@9675,9972.5 R106.1@9800,9972.5
NetR130_1: R122.2 R130.1 | length 78
  TopLayer w5: R130.1@11100,9894.5 R122.2@11100,9972.5
NetR131_1: R125.2 R131.1 | length 78
  TopLayer w5: R131.1@11300,9894.5 R125.2@11300,9972.5
NetR132_2: R132.2 U30.5 | length 732.6
  TopLayer w5: v2(11500,9800) R132.2@11500,9847.5 ; U30.5@11836.3,9286.3 11875,9325 v2(11875,9425)
  BottomLayer w5: v2(11500,9800) v2(11875,9425)
NetR135_1: C82.1 R107.2 R135.1 RV1.1 U28.4 | length 1432.7
  TopLayer w5: U28.4@10153.15,9787.6 10197.4,9787.6 10212.5,9772.5 10322.5,9772.5 10369.5,9819.5 10400,9819.5 10400,9890 10317.5,9972.5 R107.2@10275,9972.5 ; C82.1@10275,9772.5 10275,9690 10303.74,9661.26 RV1.1@10303.74,9570.28
  TopLayer w12: U28.4@10153.15,9787.6 10197.4,9787.6 10212.5,9772.5 10322.5,9772.5 10369.5,9819.5 10400,9819.5 10400,9890 10317.5,9972.5 R107.2@10275,9972.5 ; C82.1@10275,9772.5 10275,9690 10303.74,9661.26 RV1.1@10303.74,9570.28
NetR135_2: C84.1 R135.2 RV1.2 RV1.3 | length 1466.9
  TopLayer w5: 10195,9525 10240.28,9479.72 10359.72,9479.72 10375,9495 10375,9715 10400,9740 R135.2@10400,9780.5
  TopLayer w12: C84.1@9730,9525 10195,9525 10240.28,9479.72 10359.72,9479.72 10375,9495 10375,9715 10400,9740 R135.2@10400,9780.5
NetR136_1: R111.2 R136.1 | length 78
  TopLayer w5: R136.1@11400,9894.5 R111.2@11400,9972.5
NetR138_2: R138.2 U8.20 | length 78.4
  TopLayer w5: R138.2@10275,14222.5 10275,14195 10288.39,14181.61 U8.20@10288.39,14149.61
NetRS1_4: CN8.2 CN9.7 R50.1 RS1.4 | length 1120.2
  TopLayer w5: RS1.4@12420,12274.21 12549.21,12274.21 12672.5,12397.5 R50.1@12700,12397.5 12700,12275 12725,12250 12865,12250 12935,12180 12935,11915 CN9.7@13025,11825
NetRS1_6: CN8.4 CN9.9 R54.2 RS1.6 | length 1792.4
  TopLayer w5: RS1.6@12420,12254.53 12445.47,12254.53 12524,12176 12702,12176 12726,12200 12865,12200 12925,12140 12925,11825 CN9.9@13025,11725 13085,11785 13085,12140 12925,12300 R54.2@12925,12397.5
NetRS1_8: CN8.6 CN9.13 R51.1 R65.2 RS1.8 | length 1866.5
  TopLayer w5: v2(12375,11990) R65.2@12375,12022.5 ; RS1.8@12420,12234.84 12440.16,12234.84 v2(12525,12150) 12525,12130 12531,12124 12699,12124 ; 12700,12124 12726,12150 12865,12150 12915,12100 12915,11635 CN9.13@13025,11525 ; v2(12725,12300) 12725,12375 12747.5,12397.5 R51.1@12775,12397.5
  BottomLayer w5: v2(12375,11990) 12395,11990 12500,12095 12500,12125 12550,12175 12575,12175 12675,12275 12700,12275 v2(12725,12300)
NetRS1_10: CN8.8 CN9.5 R52.1 RS1.10 | length 1445.1
  TopLayer w5: RS1.10@12420,12215.16 12434.84,12215.16 12500,12150 12500,12125 12550,12075 12700,12075 12725,12100 CN8.8@12785,12100 ; R52.1@12850,12397.5 12822.5,12397.5 12775,12350 v2(12775,12300) 12800,12275 12870,12275 12945,12200 12945,12005 CN9.5@13025,11925
  BottomLayer w5: v2(12525,12100) 12690,12265 12740,12265 v2(12775,12300)
NetRS1_12: CN9.3 R74.2 R76.1 RS1.12 | length 1569.1
  TopLayer w5: R74.2@12372.5,11800 12372.5,11822.5 12400,11850 12400,12300 12410,12310 12560,12310 12675,12425 12865,12425 12885,12405 12885,12290 12955,12220 12955,12095 CN9.3@13025,12025 ; R76.1@12372.5,12100 12400,12100 ; 12400,12095 12395,12100 12400,12105 ; 12400,12190.94 12404.53,12195.47 12400,12200 ; 12400,12195 12400.47,12195.47 RS1.12@12420,12195.47
NetRS1_14: CN8.10 CN9.15 RS1.14 | length 1249.3
  TopLayer w5: RS1.14@12420,12175.79 12451.21,12175.79 12490,12137 12490,12067 12531,12026 12702,12026 12726,12050 12865,12050 12905,12010 12905,11545 CN9.15@13025,11425
NetRV2_3: R56.1 R95.2 RV2.3 | length 1673.6
  TopLayer w25: R56.1@9800,10577.5 R95.2@9800,10672.5
  BottomLayer w12: RV2.3@9550,9150 9675,9275 9675,10500 v2(9800,10625)
NetSB1_2: CN6.11 SB1.2 | length 2304.9
  TopLayer w5: v2(10510,14025) 10520,14015 10520,13759.14 10435,13674.14 10435,13490 10745,13180 10745,13067 SB1.2@10756,13056
  BottomLayer w5: CN6.11@9625,14350 9575,14300 9575,14225 9590,14210 9765,14210 9950,14025 v2(10510,14025)
NetSB2_2: CN7.24 SB2.2 | length 2559.3
  TopLayer w5: v2(12075.21,12675) 12200,12675 12230,12705 12445,12705 12465,12725 12465,13735 12450,13750 CN7.24@12425,13750
  TopLayer w8: SB2.2@11138,13050 11140,13050 v1(11160,13030)
  BottomLayer w5: v1(11160,13030) 11220,12970 11455,12970 11675,12750 12000.21,12750 v2(12075.21,12675)
NetSB3_2: CN7.23 SB3.2 | length 2659.8
  TopLayer w5: SB3.2@11243,13043 v1(11265,13021) ; v2(12125,12650) 12200,12650 12245,12695 12450,12695 12475,12720 12475,13775 12450,13800 12400,13800 12350,13750 CN7.23@12325,13750
  BottomLayer w5: v1(11265,13021) 11306,12980 11470,12980 11690,12760 12015,12760 v2(12125,12650)
NetSB4_2: CN6.15 SB4.2 | length 2053.5
  TopLayer w5: v2(10500,13975) 10500,13753.28 10425,13678.28 10425,13475 10675,13225 10675,13062 SB4.2@10687,13050
  BottomLayer w5: CN6.15@9625,14150 9650,14150 9700,14200 9750,14200 9975,13975 v2(10500,13975)
NetSB5_2: R42.1 SB5.2 | length 111.8
  TopLayer w5: R42.1@11925,13222.5 11972.5,13222.5 SB5.2@12018,13268
NetT4_3: T4.3 U6.2 | length 1176.8
  TopLayer w20: v4(11736.02,14276.02) U6.2@11736.02,14324.02 ; T4.3@11987.4,13358.66 11987.4,13387.4 v4(12000,13400)
  MidLayer1 w5: v4(11736.02,14276.02) v4@11737.05,14275
  MidLayer1 w20: v4(11736.02,14276.02) 11898.98,14276.02 12000,14175 v4(12000,13400)
NetTP9_1: C69.1 R75.2 R108.1 TP9.1 | length 782.6
  TopLayer w12: TP9.1@10525,9600 10470,9655 10470,9995 10437.5,10027.5 R108.1@10400,10027.5 10400,10180.5 10459.5,10180.5 10467.5,10172.5 C69.1@10525,10172.5
NetTR1_3: R66.1 TR1.3 U18.1 | length 504.3
  TopLayer w5: R66.1@10375,11880.5 10474.5,11880.5 10475,11880 10475,11845 10500,11820 10755,11820 10775,11840 TR1.3@10825.5,11840
NetTR2_3: R63.1 TR2.3 U18.2 | length 815.8
  TopLayer w5: R63.1@10375,11980.5 10494.5,11980.5 10525,11950 10525,11845 10540,11830 10715,11830 10770,11885 10920,11885 10965,11840 TR2.3@11025.5,11840
NetU1_1: LD7.1 R3.2 U1.1 | length 955.7
  TopLayer w5: LD7.1@9777.5,15225 9777.5,15197.5 9875,15100 9977.5,15100 ; 9977.5,15095 9972.5,15100 9977.5,15105 ; R3.2@9977.5,15150 9977.5,14997.5 10070,14905 10170,14905 10313.39,14761.61 U1.1@10400.98,14761.61
NetU1_7: LD6.1 R1.2 U1.7 | length 932.6
  TopLayer w5: LD6.1@9577.5,15225 9610,15225 9665,15170 9665,15140 9690,15115 9765,15115 9777.5,15127.5 R1.2@9777.5,15150 9800,15150 10060,14890 10160,14890 10190,14860 10190,14795 10182.2,14787.2 U1.7@10149.02,14787.2
NetU2_2: R19.2 U2.2 | length 231.3
  TopLayer w5: R19.2@10077.5,14375 10120,14375 10135,14390 10135,14475 10150.16,14490.16 10185,14490.16 10190.16,14485 U2.2@10190.16,14465.94
NetU2_3: R20.2 U2.3 | length 168.2
  TopLayer w5: R20.2@10077.5,14475 10110,14475 10135.16,14500.16 10194.84,14500.16 10209.84,14485.16 U2.3@10209.84,14465.94
NetU2_7: JP5.2 U2.7 | length 1683.2
  TopLayer w5: JP5.2@10175,13725 10215,13765 10372.57,13765 10430,13822.43 10430,13970 10295,14105 10045,14105 9940,14210 9940,14540 10000,14600 10100,14600 10150,14550 10175,14550 10190.16,14565.16 U2.7@10190.16,14584.06
NetU5_2: R11.2 U5.2 U5.3 | length 507.8
  TopLayer w5: v2(10075,14525) R11.2@10075,14572.5 ; R11.2@10077.5,14572.5 R11.2@10077.5,14575 ; U5.2@10440.16,14465.94 10440,14466.1 v2(10440,14500) 10450,14500 10459.84,14490.16 U5.3@10459.84,14465.94
  MidLayer1 w5: v2(10440,14500) v2@10440.16,14499.84
  BottomLayer w5: v2(10075,14525) 10100,14500 v2(10440,14500)
NetU6_9: C6.1 U6.9 | length 148
  TopLayer w5: U6.9@11889.57,14575.98 11889.57,14614.57 11947.5,14672.5 C6.1@11975,14672.5
NetU6_10: R18.1 U6.10 | length 101.1
  TopLayer w5: U6.10@11863.98,14575.98 11863.98,14618.98 11875,14630 R18.1@11875,14672.5
NetU6_11: R17.1 U6.11 | length 144.7
  TopLayer w5: R17.1@11775,14672.5 11812.5,14672.5 11838.39,14646.61 U6.11@11838.39,14575.98
NetU8_3: C20.1 U8.3 | length 173.7
  TopLayer w5: C20.1@10025,13955.5 10064.34,13955.5 10134.84,13885 U8.3@10134.84,13850.39
NetU8_5: CN2.6 U8.5 | length 1883.5
  TopLayer w5: CN2.6@9090,14589 9014,14589 8975,14550 8975,14200 9075,14100 9275,14100 9475,13900 9900,13900 9985,13815 10180,13815 10186.02,13821.02 U8.5@10186.02,13850.39
NetU8_6: CN2.2 U8.6 | length 1829.1
  TopLayer w5: CN2.2@9200,14534 9054,14534 9025,14505 9025,14225 9100,14150 9300,14150 9450,14000 9775,14000 9800,13975 10121.61,13975 10211.61,13885 U8.6@10211.61,13850.39
NetU8_7: CN2.8 U8.7 | length 1406.6
  TopLayer w5: CN2.8@9090,14371 9094,14371 9145,14320 9145,14280 9160,14265 9250,14265 9415,14100 9850,14100 9940,14010 10112.2,14010 10237.2,13885 U8.7@10237.2,13850.39
NetU8_8: CN5.2 U8.8 | length 1496.2
  TopLayer w5: CN5.2@9200,13184 9300,13284 9300,13525 9575,13800 10240,13800 10262.8,13822.8 U8.8@10262.8,13850.39
NetU8_9: CN2.7 U8.9 | length 1538
  TopLayer w5: CN2.7@9090,14480 9145,14425 9145,14400 9170,14375 9250,14375 9325,14300 9750,14300 9775,14275 9775,14200 9955,14020 10153.39,14020 10288.39,13885 U8.9@10288.39,13850.39
NetU8_10: CN2.3 U8.10 | length 1450.1
  TopLayer w5: CN2.3@9210,14425 9275,14425 9300,14400 9750,14400 9800,14350 9800,14200 9970,14030 10168.98,14030 10216.36,13982.61 10313.98,13885 U8.10@10313.98,13850.39
NetU8_11: CN5.3 U8.11 | length 1666.3
  TopLayer w5: CN5.3@9200,13075 9325,13200 9325,13525 9590,13790 10305,13790 10339.57,13824.57 U8.11@10339.57,13850.39
NetU8_27: C15.1 U8.27 | length 84.7
  TopLayer w5: C15.1@10100,14230.5 10100,14200 10109.25,14190.75 U8.27@10109.25,14149.61
NetU9_2: U6.3 U9.2 | length 85.5
  TopLayer w5: U9.2@11750,14243.31 11750,14254.19 11761.61,14265.81 U6.3@11761.61,14324.02
NetU9_4: T3.3 U9.4 U12.4 | length 885.5
  TopLayer w10: v5@11726.38,13491.38 U12.4@11726.38,13531.69
  TopLayer w20: v2(11700,14100) 11726.38,14126.38 U9.4@11726.38,14156.69 ; v2(11775,13400) 11787.4,13387.6 T3.3@11787.4,13358.66
  MidLayer1 w20: v2(11700,14100) 11700,13750 11725,13725 11725,13450 v2(11775,13400)
  other v5: 11725,13490
NetU10_3: U10.3 U12.1 | length 692.7
  TopLayer w5: v4@11850,13723.82 v4(11850,13725)
  TopLayer w12: U12.1@11775.59,13618.31 11775.59,13650.59 v4(11850,13725)
  TopLayer w20: U10.3@11887.6,14253.15 11887.6,14212.4 v4(11900,14200)
  MidLayer1 w20: v4(11850,13725) 11900,13775 v4(11900,14200)
NetU12_2: R33.1 U12.2 | length 89.8
  TopLayer w5: R33.1@11730.5,13700 11730.5,13674.5 11750,13655 U12.2@11750,13618.31
NetU16_2: R57.2 U16.2 | length 258.1
  TopLayer w5: R57.2@10850,12222.5 10850,12200 10875,12175 11000,12175 11039.16,12135.84 U16.2@11039.16,12115.94
NetU16_3: R58.2 U16.3 | length 189.1
  TopLayer w5: R58.2@10925,12222.5 10971.34,12222.5 11058.84,12135 U16.3@11058.84,12115.94
NetU23_20: R15.1 U23.20 | length 137.3
  TopLayer w5: R15.1@11575,10825 11634.53,10765.47 U23.20@11687.68,10765.47
NetU23_44: R93.2 U23.44 | length 88.1
  TopLayer w5: U23.44@12022.32,10824.53 R93.2@12110.47,10824.53
NetU26_3: C61.1 U21.1 U26.3 Z1.2 | length 807.7
  TopLayer w5: U26.3@9119.5,10573 U26.3@9125,10567.5
  TopLayer w20: 8900,10640 8935,10675 8900,10710 ; C61.1@9080.5,10675 9080.5,10654.5 9119.5,10615.5 U26.3@9119.5,10573
  TopLayer w30: Z1.2@8900,10574.8 8900,10760 8926.57,10786.57 U21.1@8926.57,10976.57 ; 8900,10675 9070,10675
NetU27_2: C83.1 U27.2 U27.3 | length 335
  TopLayer w5: 10675,9850 10687.2,9862.2 10687.2,9865 10702.2,9850
  TopLayer w12: C83.1@10525,9772.5 10572.5,9772.5 10650,9850 10705,9850 10712.8,9857.8 U27.3@10712.8,9890.31 ; 10687.2,9852.2 U27.2@10687.2,9890.31
NetU29_2: R128.2 U29.2 | length 453.2
  TopLayer w12: U29.2@9362.4,9514.37 9458.03,9610 9570,9610 9675,9715 R128.2@9675,9772.5
NetX1_1: C29.1 R37.1 X1.1 | length 443.5
  TopLayer w5: X1.1@10833.27,12837.01 10877.01,12837.01 10885,12845 10885,13045 10852.5,13077.5 R37.1@10852.5,13125 C29.1@10947.5,13125
OSC_IN: C54.2 U23.5 X3.2 | length 532
  TopLayer w5: U23.5@11884.53,10962.32 11884.53,11009.53 11950,11075 11950,11100 11975,11125 C54.2@12022.5,11125 12022.5,11252.5 12045,11275 X3.2@12170,11275
OSC_OUT: C53.2 U23.6 X3.1 | length 416.7
  TopLayer w5: X3.1@11795,11275 11870,11275 11902.5,11242.5 11902.5,11052.5 11864.84,11014.84 U23.6@11864.84,10962.32
PA0: CN6.9 R120.2 T3.1 T3.2 T3.5 T3.6 U11.23 | length 10358.4
  TopLayer w5: v2(9500,14450) 9650,14450 9700,14500 9750,14500 9900,14350 9900,14150 9985,14065 10185,14065 v2(10250,14000) ; U11.23@11246.85,13420.87 11246.85,13353.15 v2(11250,13350) ; v2(11450,11375) 11450,11175 11340,11065 11340,10810 11575,10575 11600,10575 11650,10525 11650,10375 11905,10120 12280,10120 12350,10050 R120.2@12350,10027.5 ; T3.1@11712.6,13358.66 T3.6@11712.6,13441.34 ; v1(11712.6,13400) 11750,13400 ; T3.2@11750,13358.66 11750,13400 ; T3.5@11750,13441.34 11750,13400
  BottomLayer w5: v2(9500,14450) 9425,14375 9425,13425 9350,13350 9350,12525 9290,12465 9290,12160 9450,12000 9925,12000 10125,11800 10125,11500 10225,11400 11425,11400 v2(11450,11375) ; v2(10250,14000) 10685,14000 10720,13965 10720,13705 11025,13400 11170,13400 11220,13350 11662.6,13350 v1(11712.6,13400)
PA4: CN7.41 R103.1 U11.29 | length 5008.4
  TopLayer w5: R103.1@10950,10227.5 10950,10775 11225,11050 v2(11225,11675) ; U11.29@11354.13,13547.83 v1(11431.17,13547.83) ; v2(12075,12650) 12060,12665 12060,12685 12085,12710 12210,12710 12265,12765 12265,12815 12300,12850 CN7.41@12325,12850
  BottomLayer w5: v2(11225,11675) 11250,11700 11700,11700 12235,12235 12235,12490 v2(12075,12650) ; v1(11431.17,13547.83) 11454,13525 11718.43,13525 11758.43,13485 11810.15,13485 12255,13040.15 12255,12895 CN7.41@12300,12850
PA5: CN7.40 R45.1 U11.30 | length 1707.5
  TopLayer w5: U11.30@11354.13,13567.52 v1(11406.52,13567.52) ; v2(11695,13550) 11695,13325 11700,13320 R45.1@11700,13277.5
  BottomLayer w5: v1(11406.52,13567.52) 11457.48,13567.52 11475,13550 11707.57,13550 11762.57,13495 11814.29,13495 12265,13044.29 12265,12935 12301,12899 12374,12899 CN7.40@12425,12950
PA8: CN6.6 U11.67 U20.20 | length 6954
  TopLayer w5: v2(10625,12325) 10641.22,12341.22 10941.22,12341.22 11050,12450 11750,12450 11776,12476 U20.20@11776,12530 ; U11.67@10971.26,14029.13 v1(10971.26,14087.26)
  BottomLayer w5: CN6.6@9700,14650 9650,14600 9600,14600 9555,14555 9555,14105 9465,14015 9465,13315 9410,13260 9410,12399.14 9370,12359.14 9370,12300 9510,12160 10031.72,12160 10206.72,12335 10490,12335 10500,12325 v2(10625,12325) ; CN6.6@9725,14650 9750,14650 9815,14585 9815,14310 10025,14100 10650,14100 10720,14170 10930,14170 10971.26,14128.74 v1(10971.26,14087.26)
PA9: CN6.7 U11.68 U20.19 | length 6953.8
  TopLayer w5: v2(10650,12325) 10950,12325 11065,12440 11840,12440 11876,12476 U20.19@11876,12530 ; U11.68@10951.57,14029.13 v1(10951.57,14101.43)
  BottomLayer w5: v2(10650,12325) 10630,12345 10202.57,12345 10027.57,12170 9515,12170 9380,12305 9380,12355 9420,12395 9420,13255.86 9475,13310.86 9475,14000 9565,14090 9565,14515 9600,14550 CN6.7@9625,14550 9675,14600 9750,14600 9805,14545 9805,14295 10010,14090 10665,14090 10735,14160 10915,14160 10951.57,14123.43 v1(10951.57,14101.43)
PA10: CN6.8 U11.69 U20.18 | length 7210.5
  TopLayer w5: v2(9525,14500) 9650,14500 9700,14550 CN6.8@9725,14550 ; U11.69@10931.89,14029.13 v1(10931.89,14087.11) ; v2(11225,11950) 11315,11860 11665,11860 11876,11649 U20.18@11876,11551
  BottomLayer w5: v2(9525,14500) 9525,14125 9445,14045 9445,13350 9390,13295 9390,12407.43 9350,12367.43 9350,12290 9500,12140 10040,12140 10215,12315 10460,12315 10475,12300 10650,12300 11010,11940 11190,11940 11200,11950 v2(11225,11950) ; CN6.8@9725,14550 9750,14550 9795,14505 9795,14280 9995,14080 10680,14080 10750,14150 10900,14150 10931.89,14118.11 v1(10931.89,14087.11)
PA11: CN6.12 R16.1 U11.70 | length 2695.9
  TopLayer w5: U11.70@10912.2,14029.13 v1(10912.2,14101.8) ; v2(11490,14125) 11575,14210 11575,14600 11625,14650 R16.1@11625,14672.5
  BottomLayer w5: CN6.12@9725,14350 9750,14350 9785,14315 9785,14265 9980,14070 10695,14070 10765,14140 10885,14140 10912.2,14112.8 10912.2,14077.8 10930,14060 11285,14060 11350,14125 v2(11490,14125)
PA12: CN6.13 R25.1 U11.71 | length 2748.4
  TopLayer w5: U11.71@10892.52,14029.13 v1(10892.52,14086.48) ; v2(11450,14110) 11565,14225 11565,14590 11525,14630 R25.1@11525,14672.5
  BottomLayer w5: CN6.13@9625,14250 9675,14300 9750,14300 9775,14275 9775,14250 9965,14060 10710,14060 10780,14130 10870,14130 10892.52,14107.48 10892.52,14077.48 10920,14050 11300,14050 11360,14110 v2(11450,14110)
PA13: CN6.14 D4.3 RS1.3 U11.72 U19.7 U23.27 | length 9488.5
  TopLayer w5: v2(9500,14200) 9675,14200 CN6.14@9725,14250 ; U11.72@10872.83,14029.13 v2(10872.83,14099.1) ; v2(11500,11725) 11500,11690 11515,11675 11515,11215 11350,11050 11350,10825 11585,10590 11780,10590 11786.1,10596.1 U23.27@11786.1,10627.68 ; U19.7@11665.16,12234.06 11665.16,12255.16 11675,12265 11675,12350 11695,12370 12155,12370 12190,12335 D4.3@12190,12274.5 12190.29,12274.21 RS1.3@12380,12274.21
  BottomLayer w5: v2(9500,14200) 9500,14125 9435,14060 9435,13360 9380,13305 9380,12411.57 9340,12371.57 9340,12285 9575,12050 10000,12050 10395,11655 11180,11655 11250,11725 11550,11725 11565,11710 11685,11710 11902,11927 11902,11960 11917,11975 11950,11975 12190,12215 v2(12190,12313) ; CN6.14@9725,14250 9750,14250 9950,14050 10725,14050 10795,14120 10851.93,14120 v2(10872.83,14099.1)
PA14: CN6.16 D3.3 RS1.5 U11.76 U23.15 U23.26 | length 8239.2
  TopLayer w5: v2(10698.78,13961.22) U11.76@10745.87,13961.22 ; v2(11712.29,11787.71) 11830,11670 11830,11480 11625,11275 11625,10975 11650,10950 11650,10875 11661.1,10863.9 11731.1,10863.9 11766.42,10828.58 U23.26@11766.42,10627.68 ; v2(11775,12025) 11890,12140 11890,12240 11924.5,12274.5 12130.5,12274.5 12175,12230 12226,12230 12250.53,12254.53 RS1.5@12380,12254.53
  BottomLayer w5: CN6.16@9700,14150 9650,14100 9600,14100 9485,13985 9485,13306.72 9430,13251.72 9430,12380.86 9550,12260.86 9550,12205 9575,12180 10023.43,12180 10198.43,12355 10645,12355 11040,11960 11165,11960 11230,12025 v2(11775,12025) 11815,11985 11815,11890.41 v2(11712.29,11787.71) ; CN6.16@9725,14150 9775,14150 9970,13955 10590.86,13955 10615.86,13980 10680,13980 v2(10698.78,13961.22)
PA15: CN6.20 D5.3 RS1.9 U11.77 U23.17 | length 7557.9
  TopLayer w5: v2(10657,13942) U11.77@10745.4,13942 ; v2(11685,11735) 11685,11690 11725,11650 11725,11425 11605,11305 11605,10945 11630,10920 11630,10845 11650.47,10824.53 U23.17@11687.68,10824.53 ; v2(11825,12000) 11924.5,12099.5 12125.5,12099.5 12175,12050 12225,12050 12250,12075 12250,12175 12290.16,12215.16 RS1.9@12380,12215.16
  BottomLayer w5: v2(10657,13942) 10642,13942 10625,13925 9925,13925 9900,13950 9700,13950 9650,13900 9600,13900 9495,13795 9495,13302.57 9440,13247.57 9440,12385 9560,12265 10094.29,12265 10194.29,12365 10660,12365 11055,11970 11150,11970 11230,12050 11775,12050 v2(11825,12000) 11825,11875 v2(11685,11735)
PB2: CN7.32 R22.2 R23.2 R24.2 R43.1 U11.37 | length 2562.4
  TopLayer w5: R22.2@11050,14427.5 v1(11077.5,14427.5) ; R23.2@11150,14427.5 11347.5,14427.5 11400,14375 11400,14125 v2(11450,14075) ; U11.37@11354.13,13705.31 v1@11430.31,13705.31 ; v1(11430,13705) 11469.5,13744.5 R43.1@11550,13744.5
  BottomLayer w5: v1(11077.5,14427.5) v1(11182.5,14427.5) ; v2(11450,14075) 11450,14050 11375,13975 11375,13730 11400,13705 11768.12,13705 12173.12,13300 12375,13300 CN7.32@12425,13350
PB3: CN6.33 D6.3 JP17.4 RS1.7 U11.89 U19.6 | length 6527.8
  TopLayer w5: v2(10645,13675) 10675.31,13705.31 U11.89@10745.87,13705.31 ; U19.6@11684.84,12234.06 11684.84,12215.16 11750,12150 11750,11925 11885,11790 12110,11790 12225,11675 12300,11675 JP17.4@12350,11625 ; 11750,12000 11800,12000 11900,12100 11900,12175 11925,12200 12225,12200 12259.84,12234.84 RS1.7@12380,12234.84 ; 12195,12200 12200,12195 12205,12200 ; D6.3@12200,12095 12200,12200
  BottomLayer w5: CN6.33@9625,13250 9530,13155 9530,12430 9590,12370 9610,12370 9635,12345 9970,12345 10050,12425 10750,12425 11045,12130 11695,12130 v2(11750,12075) ; CN6.33@9650,13250 9692.03,13292.03 9817.03,13292.03 9950,13425 10350,13425 10585,13660 10630,13660 v2(10645,13675)
PB4: CN6.34 JP10.2 U11.90 | length 3574.8
  TopLayer w5: CN6.34@9725,13250 9800,13175 10075,13175 v2(10125,13125) ; v2(10680.63,13685.63) U11.90@10745.87,13685.63
  BottomLayer w5: CN6.34@9725,13250 9800,13250 9965,13415 10365,13415 10600,13650 10645,13650 v2(10680.63,13685.63) ; v2(10125,13125) 10250,13125 10265,13140 10765,13140 10850,13225 11150,13225 11375,13000 11500,13000 11600,12900 11800,12900 JP10.2@11850,12850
